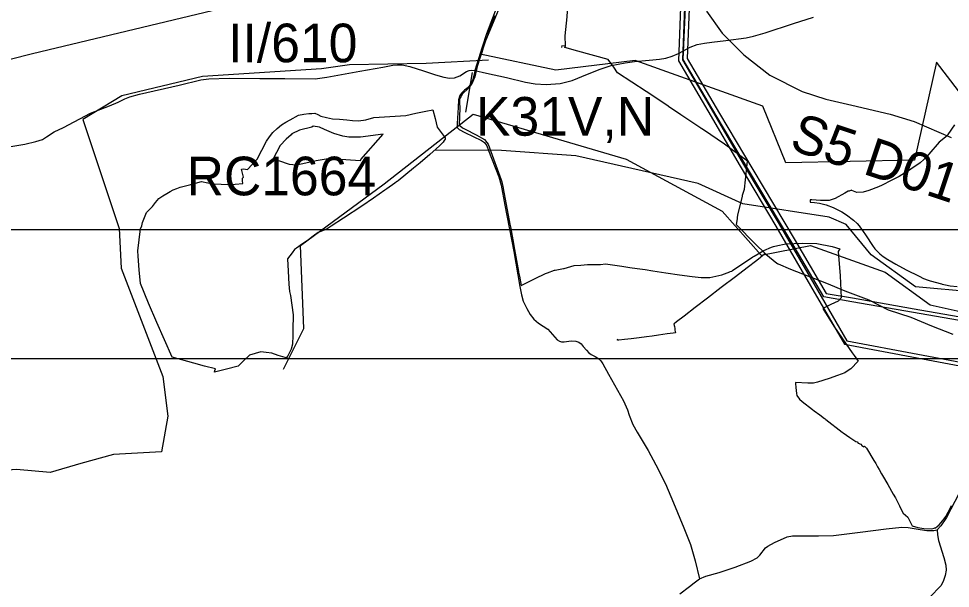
# Model space of a CAD drawing. Extents: x -789162 to -606354, y -1062736 to -945481.
# Drawn here: x -688512 to -684895, y -996869 to -994659 of the extents above; entities that cross this region are included whole.
import ezdxf

# ---------------------------------------------------------------- set-up
doc = ezdxf.new("R2010")
doc.units = 0
for name, color, linetype in [('_Rámeček', 7, 'Continuous'), ('_SIRSI VZTAHY_CYKLOTRASY MISTNI S', 7, 'Continuous'), ('_SIRSI VZTAHY_ELEKTRICKE VEDENI VN 110 kV S', 7, 'Continuous'), ('_SIRSI VZTAHY_OP vodnich zdroju II stupne', 7, 'Continuous'), ('_SIRSI VZTAHY_SILNICE I a II TRIDY_NAVRH POPIS', 7, 'Continuous'), ('_SIRSI VZTAHY_SILNICE I a II TRIDY_STAV POPIS', 7, 'Continuous'), ('_SIRSI VZTAHY_SILNICE I TRIDY_NAVRH', 7, 'Continuous'), ('_SIRSI VZTAHY_SILNICE II TRIDY_STAV', 7, 'Continuous'), ('_SIRSI VZTAHY_SILNICE III TRIDY_STAV', 7, 'Continuous'), ('_SIRSI VZTAHY_USES_NRBK_S', 7, 'Continuous'), ('_SIRSI VZTAHY_USES_popis S', 7, 'Continuous'), ('_SIRSI VZTAHY_USES_RBC_S', 7, 'Continuous'), ('_SIRSI VZTAHY_VTL PLYNOVOD', 7, 'Continuous'), ('_SIRSI VZTAHY_ZELEZNICE NAVRH', 7, 'Continuous')]:
    doc.layers.add(name, color=color, linetype=linetype)

msp = doc.modelspace()

# ---------------------------------------------------------------- linework, layer by layer
at = {"layer": '_Rámeček'}
msp.add_line((-694376.9, -995477.3), (-674375.7, -995477.3), dxfattribs=at)
msp.add_lwpolyline([(-673887.2, -995977.3), (-673887.2, -966277.3), (-694887.2, -966277.3), (-694887.2, -995977.3)], close=True, dxfattribs=at)
at = {"layer": '_SIRSI VZTAHY_CYKLOTRASY MISTNI S'}
msp.add_line((-686776.4, -995021.5), (-686749.9, -994867.4), dxfattribs=at)
for points in [[(-684053.5, -995624.9), (-684491.2, -995009), (-684778.4, -995050.1), (-684949.4, -994827.6), (-685034.9, -995207.5), (-685534.2, -995217.7), (-685623.1, -994998.7), (-686119, -994820.8), (-686426.8, -994858.4), (-686720.9, -994796.8), (-686546.4, -994375.9), (-686577.2, -993920.8), (-686738, -993777.1), (-687381.5, -994136), (-687477.3, -993800.6), (-687483.2, -993028.1)], [(-686688.1, -994819.6), (-686929.8, -994832.8), (-687227.1, -994838.2), (-687336, -994854.1), (-687798, -994883.3), (-688111.3, -994957.7), (-688262.7, -995050.7), (-688121.9, -995473.2), (-688114, -995627.3), (-687952, -996047.1), (-687933.4, -996201.2), (-687957.3, -996339.4), (-688143.2, -996350), (-688270.6, -996384.6), (-688390.1, -996419.1), (-688520.2, -996408.5), (-688671.6, -996419.1), (-688801.7, -996504.1), (-688902.6, -996591.8), (-688905.2, -996381.9), (-688966.3, -996089.6), (-688982.2, -995983.4)], [(-687483.5, -996018.5), (-687404.8, -995861.1), (-687418.5, -995539.4), (-687093.6, -995299.9), (-686748.2, -995029.5), (-686153.2, -995204), (-685780.4, -995405.9), (-685630, -995577), (-685438.5, -995539.4), (-685147.8, -995642), (-684973.4, -995768.7), (-684344.1, -995909), (-684060.3, -995611.2), (-683673.9, -996025.3)]]:
    msp.add_lwpolyline(points, dxfattribs=at)
at = {"layer": '_SIRSI VZTAHY_ELEKTRICKE VEDENI VN 110 kV S'}
for points in [[(-684808.5, -995839.1), (-685038.4, -995799.1), (-685278, -995757.4), (-685386.1, -995738.6), (-685515, -995521.3), (-685674.8, -995252.1), (-685803.8, -995034.6), (-685932.5, -994817.9), (-685922.3, -994585.9), (-685909.9, -994304.2), (-685900.6, -994091.1), (-686054.2, -993906.6), (-686148.6, -993793.5), (-686145.8, -993785.2)], [(-684808.5, -995839.1), (-685038.4, -995799.1), (-685278, -995757.4), (-685386.1, -995738.6), (-685515, -995521.3), (-685674.8, -995252.1), (-685803.8, -995034.6), (-685932.5, -994817.9), (-685922.3, -994585.9), (-685909.9, -994304.2), (-685900.6, -994091.1), (-686054.2, -993906.6), (-686148.6, -993793.5), (-686145.8, -993785.2)], [(-686144.4, -993784.8), (-686137.8, -993783), (-686042.7, -993897), (-685885.3, -994086.1), (-685894.9, -994304.9), (-685907.3, -994586.4), (-685917.4, -994814), (-685790.9, -995026.9), (-685661.9, -995244.4), (-685502.1, -995513.6), (-685376.7, -995725), (-685275.7, -995742.5), (-685035.9, -995784.3), (-684805.8, -995824.3)], [(-686144.4, -993784.8), (-686137.8, -993783), (-686042.7, -993897), (-685885.3, -994086.1), (-685894.9, -994304.9), (-685907.3, -994586.4), (-685917.4, -994814), (-685790.9, -995026.9), (-685661.9, -995244.4), (-685502.1, -995513.6), (-685376.7, -995725), (-685275.7, -995742.5), (-685035.9, -995784.3), (-684805.8, -995824.3)], [(-685930.6, -994313.4), (-685939.6, -994544.9), (-685950.8, -994822.5), (-685836.9, -995016.8), (-685710.8, -995231.7), (-685573.2, -995464.2), (-685438.6, -995695.3), (-685306.4, -995922.2), (-685024.6, -995974.9), (-684755, -996025.3)], [(-685915.3, -994313.6), (-685924.6, -994545.5), (-685935.6, -994818.7), (-685824, -995009.2), (-685697.8, -995224.1), (-685560.3, -995456.6), (-685425.6, -995687.8), (-685296.9, -995908.7), (-685021.9, -995960.1), (-684752.2, -996010.5)]]:
    msp.add_lwpolyline(points, dxfattribs=at)
at = {"layer": '_SIRSI VZTAHY_OP vodnich zdroju II stupne'}
for points in [[(-686664, -994648.5), (-686674.9, -994676.4), (-686678.4, -994685.7), (-686685.4, -994703.8), (-686689.5, -994715.1), (-686693.9, -994727.7), (-686698.7, -994741.6), (-686704.9, -994760.8), (-686708.3, -994771.9), (-686714.5, -994789.5), (-686721.7, -994812.7), (-686730.5, -994840.8), (-686732, -994845.6), (-686734.6, -994855.2), (-686740.7, -994884.6), (-686742.9, -994889), (-686746.1, -994896.6), (-686751.1, -994908.8), (-686756.7, -994918.3), (-686766.5, -994930), (-686789.3, -994950), (-686795.4, -994961.7), (-686800.6, -994969.7), (-686800.3, -994983.8), (-686799.4, -995005.9), (-686801.6, -995072.6), (-686798.8, -995072.8), (-686789, -995082.7), (-686779.2, -995087.6), (-686736, -995109.6), (-686703.8, -995128.1), (-686690, -995145.3), (-686684.5, -995160.2), (-686638.6, -995283.8), (-686635.8, -995291.6), (-686631.3, -995316.3), (-686629.6, -995325.5), (-686627.1, -995339), (-686604.8, -995456.5), (-686603.1, -995466), (-686591.4, -995530.5), (-686589.8, -995539.7), (-686574.2, -995625.6), (-686573.2, -995631), (-686571.1, -995642.4), (-686568.3, -995658), (-686561.8, -995693.8), (-686546.4, -995686.2), (-686541.2, -995683.7), (-686507.4, -995667.1), (-686467.1, -995647.8), (-686459.6, -995644.8), (-686431.6, -995635.2), (-686429.6, -995634.5), (-686396.5, -995628.6), (-686394.2, -995628), (-686356, -995617), (-686329.2, -995615), (-686303.7, -995613.1), (-686300.8, -995612.8), (-686284.1, -995612.6), (-686277.9, -995612.5), (-686264.8, -995612.3), (-686253.8, -995612.2), (-686234.2, -995609.4), (-686170.4, -995618.9), (-686139, -995623.6), (-686111.3, -995627.7), (-686079.9, -995632.4), (-686050.6, -995636.7), (-685999.8, -995644.3), (-685946.7, -995652.2), (-685896.9, -995659.4), (-685862.2, -995663), (-685828.5, -995663.1), (-685805.3, -995658.4), (-685781.7, -995652.2), (-685751.9, -995641), (-685749.8, -995640.2), (-685743.8, -995637.9), (-685741.3, -995636.2), (-685661.4, -995583.1), (-685656.9, -995580.2), (-685619.6, -995558.1), (-685589.5, -995545.4), (-685581.9, -995543.4), (-685565.1, -995539.5), (-685540.8, -995533.9), (-685532, -995531.8), (-685471.1, -995529.3), (-685413.6, -995531.4), (-685354.1, -995543), (-685324.8, -995552.2), (-685330.1, -995561.8), (-685323, -995656.6), (-685319.4, -995742.1), (-685330.1, -995754.8), (-685358.6, -995768.2), (-685389.8, -995783.2), (-685347.5, -995851.2), (-685299.4, -995922.2), (-685275.9, -995955.4), (-685268, -995965.6), (-685252.6, -995987.5), (-685281.8, -996016.8), (-685292, -996024.4), (-685305.3, -996032.5), (-685333.8, -996043.7), (-685366.2, -996055), (-685410.5, -996069.7), (-685426.4, -996073.1), (-685433.7, -996073), (-685444.9, -996073), (-685448.3, -996072.7), (-685496.6, -996070.3), (-685496.8, -996074.2), (-685495.3, -996089.5), (-685493.1, -996112.7), (-685491.8, -996121.3), (-685481.3, -996134.8), (-685471, -996143.7), (-685430.1, -996175.3), (-685423.7, -996180.5), (-685402.3, -996196.1), (-685383.2, -996209.7), (-685380.6, -996211.6), (-685378.1, -996213.4), (-685314.6, -996262.7), (-685311.1, -996265.4), (-685285.2, -996283.4), (-685261.5, -996299.8), (-685257.2, -996301), (-685252.8, -996306.1), (-685242.9, -996310.2), (-685239.2, -996314.8), (-685231.5, -996319.9), (-685228.3, -996317.8), (-685220.2, -996324.8), (-685192, -996373.3), (-685185.1, -996385.1), (-685178.1, -996397.2), (-685171.6, -996408.3), (-685162.2, -996424.7), (-685158.9, -996430.6), (-685138.4, -996466.2), (-685116.8, -996503.8), (-685108.8, -996517.7), (-685092.4, -996548.6), (-685088.2, -996557.3), (-685078.4, -996577.5), (-685060.9, -996592.8), (-685044.7, -996623.9), (-685043.2, -996626.8), (-685021.5, -996632.6), (-684998.1, -996636.8), (-684966.7, -996637.8), (-684958, -996635.5), (-684955, -996634.7), (-684953.4, -996633.8), (-684945.9, -996629.3), (-684938.1, -996622.8), (-684918.7, -996599.1), (-684912.3, -996590.2), (-684903.8, -996573.8), (-684900.7, -996567.7), (-684890.5, -996547.2)], [(-684878.6, -995071), (-684904.5, -995108.4), (-684906.1, -995110.5), (-684908.1, -995112.8), (-684938.7, -995138.1), (-684978.3, -995184.7), (-684984.7, -995191.8), (-684998.7, -995205.6), (-685013, -995218), (-685048.5, -995242.7), (-685066.7, -995255.3), (-685072.7, -995258.8), (-685093.8, -995271.3), (-685125, -995287.1), (-685160.5, -995304.7), (-685173.6, -995311), (-685212.3, -995325.2), (-685234, -995331.5), (-685258, -995333), (-685277.2, -995325), (-685279.1, -995324.2), (-685287.5, -995327.6), (-685288.6, -995327.8), (-685292.1, -995328.3), (-685304.2, -995335.6), (-685342.8, -995356.8), (-685365.8, -995364.9), (-685399.4, -995364.3), (-685432.6, -995362.3), (-685439.5, -995362), (-685439.9, -995371.2), (-685422.7, -995372.5), (-685403.2, -995374.7), (-685377.8, -995381.2), (-685350.6, -995391), (-685316.3, -995408.4), (-685298.2, -995420.2), (-685271.1, -995440.4), (-685257.2, -995453.8), (-685249.7, -995462.5), (-685246.6, -995466.1), (-685235.9, -995480.6), (-685222.3, -995501.5), (-685197.2, -995539.3), (-685187.9, -995551.6), (-685178.4, -995562.3), (-685169, -995571.3), (-685155.9, -995581.6), (-685138.5, -995593.4), (-685106.7, -995611.7), (-685067.2, -995632.7), (-685016.5, -995658.3), (-685000, -995666.4), (-684981.5, -995673.7), (-684973.6, -995675.8), (-684929.5, -995687.7), (-684926.4, -995688.6), (-684913.7, -995691.9), (-684895.3, -995695.1), (-684868.4, -995698.4)]]:
    msp.add_lwpolyline(points, dxfattribs=at)
msp.add_lwpolyline([(-687183.4, -995204.7), (-687097.5, -995106.4), (-687184.9, -995118.9), (-687230.4, -995119.2), (-687253.2, -995115), (-687288.6, -995104.7), (-687324.5, -995088.4), (-687343.7, -995079.9), (-687368.3, -995075.3), (-687374.2, -995080.4), (-687421.4, -995090.8), (-687451.1, -995106), (-687453.7, -995109.2), (-687474.2, -995126.8), (-687496.3, -995151.5), (-687525.7, -995205), (-687499, -995209.9), (-687465.6, -995221.5), (-687461.5, -995222.8), (-687434, -995226.2), (-687396.9, -995218.7), (-687357.1, -995208.6), (-687318.9, -995202.3), (-687284.6, -995201.9), (-687280.7, -995202.8), (-687184.6, -995209.4)], close=True, dxfattribs=at)
at = {"layer": '_SIRSI VZTAHY_SILNICE I TRIDY_NAVRH'}
msp.add_lwpolyline([(-685841.6, -994630.1), (-685780.6, -994715.4), (-685697.2, -994799.4), (-685595.4, -994877.9), (-685471, -994941.1), (-685378.5, -994971), (-685277.1, -994994.4), (-685129.4, -995029.3), (-685035.4, -995057.9), (-684892, -995119.6)], dxfattribs=at)
at = {"layer": '_SIRSI VZTAHY_SILNICE II TRIDY_STAV'}
for points in [[(-686740.6, -994860.1), (-686695.4, -994870.3), (-686617.9, -994887.2), (-686544.3, -994905.2), (-686506.6, -994911.6), (-686464.4, -994914.2), (-686409.4, -994910.2), (-686362.9, -994898.3), (-686304.2, -994873.6), (-686254.4, -994854.8), (-686211.6, -994841.2), (-686158.2, -994829.9), (-686121.3, -994824.5), (-686050.1, -994818.6), (-686024.5, -994815.4), (-686000.3, -994812.1), (-685974.7, -994804.4), (-685950.7, -994793.4), (-685904.7, -994769.9), (-685877.7, -994759.3), (-685849.8, -994753.6), (-685821.5, -994750.3), (-685766.5, -994744.2), (-685688.4, -994732.7), (-685659.8, -994726.6), (-685614.6, -994714.2), (-685504.3, -994677.9), (-685427, -994653)], [(-688542.7, -995155), (-688487.4, -995145.2), (-688444.9, -995136), (-688419.4, -995128.2), (-688403.5, -995117.5), (-688374.1, -995097.4), (-688338.1, -995080.6), (-688232.8, -995025.1), (-688159.2, -994996.6), (-688125.4, -994983), (-688099.8, -994969.9), (-688081, -994962.6), (-688042.8, -994952.4), (-687888.9, -994916.3), (-687805.3, -994896.2), (-687774.1, -994892.2), (-687695.1, -994889.6), (-687576.2, -994890.4), (-687478.8, -994891.4), (-687360.7, -994892.2), (-687315.2, -994886.4), (-687188.2, -994862.7), (-687098, -994846.9), (-687058.9, -994839.7), (-687041.8, -994838), (-687023.8, -994837.7), (-686992.9, -994844.5), (-686939.9, -994861.8), (-686894.1, -994876.4), (-686861.8, -994885.6), (-686839.9, -994890.1), (-686820.6, -994888.9), (-686798.8, -994881.2), (-686773.2, -994864.2), (-686763.1, -994860.5), (-686753, -994859), (-686740.6, -994860.1)]]:
    msp.add_lwpolyline(points, dxfattribs=at)
at = {"layer": '_SIRSI VZTAHY_SILNICE III TRIDY_STAV'}
for points in [[(-686732.7, -993827.1), (-686723, -993841.3), (-686657.3, -993894.6), (-686643.8, -993911), (-686637.1, -993934.3), (-686627.3, -993998.1), (-686601.6, -994192.4), (-686587.5, -994304.5), (-686585.5, -994332.7), (-686586.5, -994357.5), (-686591.6, -994383.2), (-686623.6, -994501.3), (-686642, -994566.9), (-686662.8, -994629.4), (-686695.3, -994718.2), (-686713.1, -994769.8), (-686740.6, -994860.1)], [(-686740.6, -994860.1), (-686742.5, -994867.2), (-686748.5, -994894.8), (-686756.8, -994911.6), (-686767.2, -994925.3), (-686781.5, -994936.7), (-686793.2, -994947.6), (-686799.2, -994957.3), (-686804, -994974.2), (-686805.5, -995004.1), (-686809.2, -995065.9), (-686809.2, -995080.5), (-686802.2, -995088.5), (-686779.6, -995100.5), (-686714.9, -995131.7), (-686703.4, -995139.6), (-686694.9, -995152), (-686687.6, -995170.7), (-686648.6, -995273), (-686639.4, -995304.9), (-686625.2, -995382), (-686590.2, -995562.3), (-686567, -995698.3), (-686560.2, -995730.6), (-686553.1, -995754.7), (-686539.8, -995783.9), (-686526.4, -995806), (-686511.5, -995825.3), (-686493.6, -995840), (-686458.3, -995864.1), (-686430.4, -995894.9), (-686422.1, -995904.8), (-686412.9, -995909.9), (-686404.3, -995912.1), (-686394.8, -995912.1), (-686367.1, -995908.3), (-686349.1, -995909.5), (-686336.9, -995914.5), (-686328.8, -995920), (-686320.2, -995931.1), (-686307.8, -995944.9), (-686298.3, -995955.9), (-686289.6, -995961.8), (-686274.5, -995969.1), (-686263.4, -995976.2), (-686252.3, -995986.9), (-686244.6, -995997.8), (-686222.1, -996038.1), (-686163.9, -996141.1), (-686148.1, -996175.9), (-686141.7, -996196.8), (-686128.4, -996233.7), (-686111.6, -996262.6), (-686068.8, -996334.5), (-686037.9, -996389.6), (-686001.4, -996463.9), (-685970.3, -996537.2), (-685930.3, -996634.1), (-685904.2, -996698.5), (-685885.5, -996762.4), (-685868.5, -996831.4)], [(-684556.9, -996049.4), (-684574.9, -996081.9), (-684593.9, -996118.4), (-684624.5, -996171.5), (-684641.9, -996189.2), (-684669.8, -996213.7), (-684723.8, -996261.9), (-684746.8, -996285.8), (-684766, -996312.9), (-684785.9, -996349.9), (-684861.1, -996499.2), (-684910.4, -996594.1), (-684932.2, -996626.8), (-684946.8, -996641.8)], [(-685868.5, -996831.4), (-685844.3, -996821.7), (-685792.5, -996807.7), (-685731.2, -996787), (-685669.6, -996763.9), (-685645.8, -996750.2), (-685634.9, -996739.8), (-685613.4, -996712.1), (-685603.6, -996705.2), (-685577.9, -996690.6), (-685528.3, -996668.7), (-685507.4, -996664.8), (-685406.9, -996664.8), (-685349.3, -996664.2), (-685245.4, -996651.5), (-685144.2, -996637.9), (-685083.7, -996631.3), (-685058.6, -996632.7), (-685011.9, -996640.4), (-684986.6, -996644.6), (-684959.6, -996644.4), (-684946.8, -996641.8)], [(-684946.8, -996641.8), (-684945.5, -996661.5), (-684941.4, -996682.9), (-684920.1, -996749.3), (-684913.1, -996778.9), (-684911.6, -996798.8), (-684915.3, -996818.7), (-684921.9, -996838.2), (-684931.1, -996857.8), (-684975.9, -996905)], [(-685945.5, -996890.3), (-685908.2, -996861.9), (-685890, -996847.7), (-685868.5, -996831.4)]]:
    msp.add_lwpolyline(points, dxfattribs=at)
at = {"layer": '_SIRSI VZTAHY_USES_NRBK_S'}
msp.add_lwpolyline([(-684800.9, -995719.9), (-685030, -995698.7), (-685203, -995575.7), (-685300.1, -995457.3), (-685365.4, -995428.4), (-685700.7, -995376.8), (-685873.6, -995297.8), (-686348.9, -995190.4), (-686637.2, -995170.7), (-686896.9, -995169.2)], dxfattribs=at)
at = {"layer": '_SIRSI VZTAHY_USES_RBC_S'}
msp.add_lwpolyline([(-688033.9, -995462.8), (-688031.5, -995449.4), (-688023.3, -995430.3), (-688015.1, -995411.1), (-688003.8, -995399.2), (-687992.5, -995387.3), (-687980.4, -995371.8), (-687968.3, -995356.3), (-687952.6, -995346.5), (-687936.9, -995336.6), (-687924.3, -995330), (-687911.6, -995323.4), (-687898.6, -995318.3), (-687885.6, -995313.2), (-687844.1, -995302), (-687802.5, -995290.9), (-687777.2, -995295.6), (-687751.8, -995300.2), (-687726.5, -995301.5), (-687701.2, -995302.8), (-687671.3, -995300.6), (-687641.4, -995298.5), (-687642.5, -995288), (-687643.5, -995277.6), (-687639.1, -995273.9), (-687642.8, -995258.5), (-687646.5, -995243), (-687639.3, -995241.2), (-687624.3, -995244.6), (-687604.9, -995224.4), (-687585.5, -995204.1), (-687567.9, -995168.9), (-687550.4, -995133.7), (-687538, -995117), (-687525.6, -995100.3), (-687508.8, -995085.2), (-687492.1, -995070.2), (-687475.3, -995060.5), (-687458.5, -995050.8), (-687425.3, -995033.8), (-687405.5, -995028.9), (-687385.7, -995027.2), (-687374, -995026.3), (-687362.3, -995025.3), (-687350.5, -995031.2), (-687338.7, -995037.2), (-687316.4, -995042.2), (-687294, -995047.3), (-687266.1, -995049.4), (-687238.1, -995051.5), (-687215.8, -995053.3), (-687193.4, -995055.1), (-687164.8, -995051.1), (-687132.8, -995042), (-687070.6, -995038.1), (-687008.5, -995034.3), (-686969.8, -995026.1), (-686931.1, -995017.8), (-686904.3, -995012.9), (-686895.7, -995046.3), (-686887.1, -995079.8), (-686871.5, -995100.8), (-686855.9, -995121.8), (-686856.2, -995124.1), (-686856.4, -995126.4), (-686860.1, -995132), (-686863.8, -995137.6), (-686869.4, -995143.6), (-686877.7, -995152.6), (-686915.6, -995185.4), (-686953.5, -995218.1), (-686978.7, -995238.6), (-687009, -995263.2), (-687039.3, -995287.8), (-687043.1, -995290.5), (-687044.7, -995291.6), (-687051.8, -995296.7), (-687082.4, -995318.5), (-687090.5, -995324.3), (-687135.1, -995355.3), (-687179.7, -995386.3), (-687250.8, -995433.1), (-687298.5, -995464.2), (-687315, -995474.7), (-687332.2, -995481.8), (-687349.5, -995488.9), (-687368.4, -995502.9), (-687387.3, -995516.8), (-687410.4, -995532.8), (-687433.5, -995548.7), (-687441.3, -995554.1), (-687449.7, -995567.9), (-687458.9, -995579.6), (-687468, -995591.2), (-687465.8, -995638.4), (-687462.8, -995688.3), (-687460.9, -995717.5), (-687456.8, -995732.8), (-687451.9, -995770.4), (-687447, -995808), (-687446.3, -995827.8), (-687447.1, -995847), (-687447.9, -995866.1), (-687448.2, -995888.1), (-687448.8, -995921.9), (-687454.5, -995941.2), (-687464.5, -995961.4), (-687471, -995974.5), (-687468.9, -995968.2), (-687471.2, -995974.7), (-687477, -995974), (-687504.3, -995965.3), (-687529.6, -995957.2), (-687550.6, -995954.4), (-687571.6, -995951.6), (-687593.7, -995957.7), (-687615.8, -995963.8), (-687637.8, -995985.3), (-687659.9, -996006.9), (-687705.8, -996018.6), (-687751.7, -996030.4), (-687750, -996024.2), (-687748.2, -996017.9), (-687790.1, -996006.5), (-687832, -995995), (-687915.8, -995972.1), (-687945.7, -995905), (-687975.7, -995837.9), (-688007.4, -995762), (-688039.2, -995686.1), (-688043.6, -995633.5), (-688047.9, -995580.8), (-688049.8, -995559.1), (-688044.5, -995516.7), (-688039.2, -995474.4)], close=True, dxfattribs=at)
at = {"layer": '_SIRSI VZTAHY_VTL PLYNOVOD'}
for points in [[(-686389.8, -994763.8), (-686389.9, -994725.1), (-686383, -994651.6), (-686373.3, -994494.9), (-686364, -994343.7), (-686364, -994343.6), (-686364, -994342.8), (-686363.7, -994339.2)], [(-686390.7, -994764.7), (-686393, -994765.2), (-686404, -994763.9), (-686404.4, -994768.8), (-686404.4, -994769), (-686404.4, -994770.1)], [(-685992.1, -994997.5), (-686076.5, -994940.8), (-686187.1, -994868.6), (-686201.3, -994847.5), (-686201.7, -994847), (-686201.7, -994846.9), (-686209.5, -994836.1), (-686223.1, -994817.1), (-686340.7, -994784.6), (-686391.6, -994770.5), (-686389.8, -994764.7)], [(-686390.7, -994764.7), (-686390.8, -994763.8), (-686390, -994763.8), (-686389.8, -994763.8)], [(-686389.8, -994764.7), (-686390.3, -994764.7), (-686390.7, -994764.7)], [(-686389.8, -994764.7), (-686389.8, -994763.8)], [(-685989.7, -994999.1), (-685989.3, -994998.5), (-685989.8, -994998.1), (-685990.5, -994997.5), (-685990.7, -994997.3), (-685991.1, -994997.1), (-685991.6, -994996.7), (-685992.1, -994997.5)], [(-685989.7, -994999.1), (-685990.6, -994998.5), (-685992.1, -994997.5)], [(-685614.1, -995569.9), (-685614.7, -995569.3), (-685653.5, -995531.9), (-685725, -995458.7), (-685721.5, -995433.5), (-685721, -995429.9), (-685719.7, -995420.7), (-685702.6, -995347.8), (-685701.5, -995344.2), (-685694.3, -995319.9), (-685683.3, -995211.5), (-685771.8, -995146.2), (-685854, -995090.4), (-685860.2, -995086.2), (-685860.6, -995085.9), (-685861.3, -995085.5), (-685862.5, -995084.7), (-685863.7, -995083.9), (-685864.2, -995083.6), (-685941.1, -995032.4), (-685989.7, -994999.1)], [(-685614.6, -995570.4), (-685614.8, -995570.7), (-685618.8, -995574.3), (-685622.7, -995577.3), (-685632.8, -995585.5), (-685647, -995596.9), (-685683.9, -995625.4), (-685729.6, -995659.9), (-685785.1, -995702.4), (-685838.2, -995742.9), (-685885.5, -995779.2), (-685928.6, -995812.4), (-685957.9, -995834.8), (-685967.7, -995842.4), (-685968.6, -995842.9), (-685967.3, -995849.7), (-685966.6, -995852.9), (-685966.5, -995853.4), (-685965.4, -995860.6), (-685964.4, -995867.4), (-685962.1, -995877.2), (-685971.1, -995878.7), (-685994.6, -995882.2), (-686028.6, -995886.9), (-686052.9, -995890.4), (-686074.7, -995893), (-686103.2, -995896.5), (-686133.8, -995900.6), (-686160.6, -995903.2), (-686182.7, -995905.8), (-686183.1, -995905.9), (-686187.3, -995906.3), (-686187.9, -995903.9), (-686188.2, -995902.9), (-686188.2, -995902.9), (-686188.3, -995902.6)], [(-685614.6, -995570.4), (-685614.3, -995570.1), (-685614.1, -995569.9)], [(-685614.6, -995570.4), (-685614.1, -995571), (-685613.9, -995570.8), (-685613.6, -995570.4)], [(-685614.1, -995569.9), (-685613.6, -995570.4)], [(-685613.6, -995570.4), (-685612, -995571.9), (-685569.4, -995607.7), (-685567.1, -995608.6), (-685565.4, -995609.2), (-685564.6, -995609.5), (-685564.5, -995609.6), (-685563.3, -995610), (-685516.3, -995631.1), (-685375.4, -995685.1), (-685305.4, -995714.6), (-685211.3, -995749.3), (-685136.7, -995788.4), (-685049, -995817.4), (-684968.2, -995850), (-684885.2, -995882.6)]]:
    msp.add_lwpolyline(points, dxfattribs=at)
at = {"layer": '_SIRSI VZTAHY_ZELEZNICE NAVRH'}
msp.add_lwpolyline([(-686682.5, -994344.6), (-687485.4, -994561.6), (-688457.9, -994794.7), (-689372.2, -995027.4)], dxfattribs=at)

# ---------------------------------------------------------------- texts
at = {"layer": '_SIRSI VZTAHY_SILNICE I a II TRIDY_NAVRH POPIS'}
msp.add_text('S5 D01C', height=150, rotation=341.5529, dxfattribs=at).set_placement((-685525, -995163.9))
at = {"layer": '_SIRSI VZTAHY_SILNICE I a II TRIDY_STAV POPIS'}
msp.add_text('II/610', height=150, dxfattribs=at).set_placement((-687698.8, -994828.1))
at = {"layer": '_SIRSI VZTAHY_USES_popis S'}
for s, p in [('K31V,N', (-686736.6, -995112.9)), ('RC1664', (-687860, -995344.3))]:
    msp.add_text(s, height=150, dxfattribs=at).set_placement(p)

doc.saveas('drawing.dxf')
